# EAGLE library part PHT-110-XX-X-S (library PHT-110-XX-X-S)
.100 PRESS FIT SOCKET ASSEMBLY.
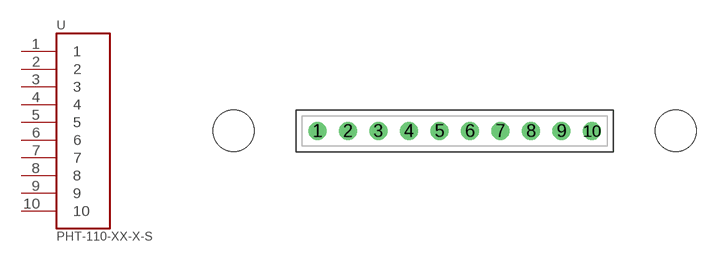
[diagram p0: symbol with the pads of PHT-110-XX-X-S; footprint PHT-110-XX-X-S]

Designator prefix -

## PHT-110-XX-X-S  [PHT-110-XX-X-S]
1  1
2  2
3  3
4  4
5  5
6  6
7  7
8  8
9  9
10  10

## Footprint PHT-110-XX-X-S (pad centres in mm)
.100 PRESS FIT SOCKET ASSEMBLY.
drill 0.991 pad 1.499 round: 1 -11.43,0; 2 -8.89,0; 3 -6.35,0; 4 -3.81,0; 5 -1.27,0; 6 1.27,0; 7 3.81,0; 8 6.35,0; 9 8.89,0; 10 11.43,0
hole 3.429 at -18.415,0
hole 3.429 at 18.415,0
